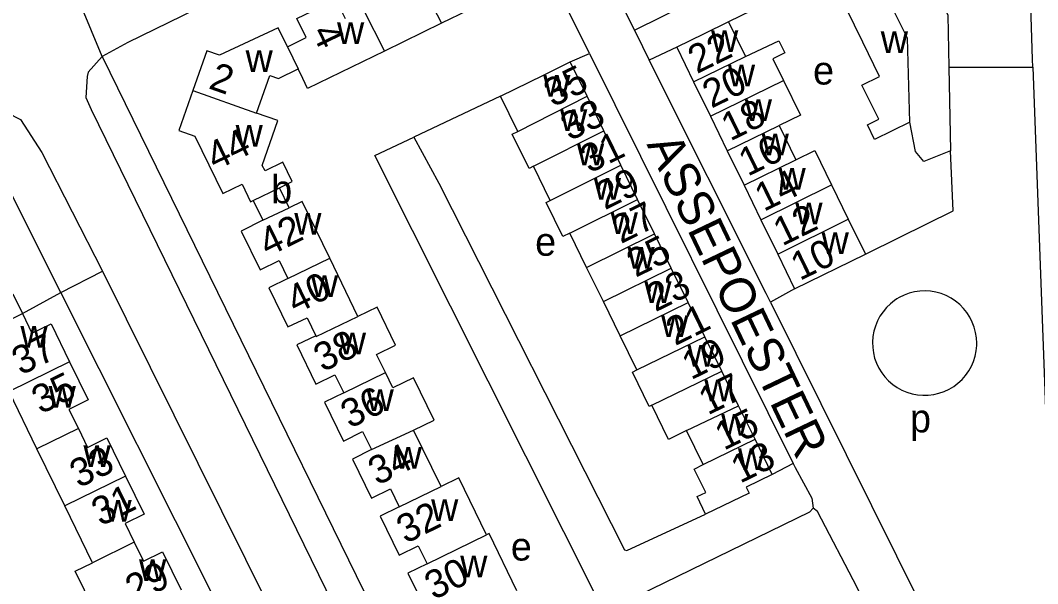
# Model space of a CAD drawing. Extents: x 159441 to 162086, y 388175 to 389787.
# Drawn here: x 161694.2 to 161838.6, y 388623.7 to 388703.5 of the extents above; entities that cross this region are included whole.
import ezdxf

# ---------------------------------------------------------------- set-up
doc = ezdxf.new("R2010")
doc.units = 0
for name, color, linetype in [('BLT_Basislijn', 7, 'Continuous'), ('BLT_Bebouwing', 7, 'Continuous'), ('BLT_Centroide', 7, 'Continuous'), ('BLT_Huisnummer', 7, 'Continuous'), ('BLT_Huisnummer_ tussenligend', 7, 'Continuous'), ('BLT_Onderverdeling_panden', 7, 'Continuous'), ('BLT_Straatnaam', 7, 'Continuous'), ('BLT_Vlakafsluiter', 7, 'Continuous')]:
    doc.layers.add(name, color=color, linetype=linetype)

msp = doc.modelspace()

# ---------------------------------------------------------------- linework, layer by layer
at = {"layer": 'BLT_Basislijn'}
for p, q in [((161787.37, 388699.71), (161783.47, 388697.87)), ((161774.98, 388698.85), (161803.89, 388640.69)), ((161826, 388696.91), (161826.22, 388685.02)), ((161837.9, 388696.91), (161841.3, 388605.81)), ((161699.94, 388664.93), (161705.87, 388667.98)), ((161705.87, 388667.98), (161767.18, 388544.52)), ((161694.49, 388661.96), (161699.94, 388664.93)), ((161804.09, 388665.47), (161800.65, 388663.59)), ((161800.65, 388663.59), (161829.12, 388606.33)), ((161803.89, 388640.69), (161800.93, 388639.14))]:
    msp.add_line(p, q, dxfattribs=at)
for points in [[(161837.9, 388696.91), (161837.86, 388698.05), (161834.76, 388795.59)], [(161785.58, 388747.05), (161785.56, 388745.89), (161785.48, 388744.73), (161785.31, 388743.59), (161785.06, 388742.46), (161784.74, 388741.34), (161784.34, 388740.26), (161783.86, 388739.2), (161783.31, 388738.18), (161782.7, 388737.2), (161782.02, 388736.27), (161781.27, 388735.38), (161780.29, 388734.37), (161768.65, 388728.46), (161769.65, 388725.53), (161772.18, 388720.46), (161781.36, 388702.15)], [(161774.98, 388698.85), (161774.36, 388700.1), (161762.24, 388724.2), (161759.59, 388724.85), (161709.46, 388700.41), (161705.83, 388698.4)], [(161781.36, 388702.15), (161809.35, 388715.97), (161808.82, 388717), (161817.35, 388721.8)], [(161817.35, 388721.8), (161825.86, 388704.28), (161826, 388696.91)], [(161808.03, 388709.84), (161794.7, 388703.31)], [(161781.36, 388702.15), (161782.49, 388699.82), (161783.47, 388697.87)], [(161705.83, 388698.4), (161703.83, 388696.17), (161703.67, 388695.55), (161703.52, 388692.57), (161704.25, 388690.87), (161758.4, 388580.27)], [(161705.83, 388698.4), (161762.65, 388582.4)], [(161772.25, 388697.63), (161774.98, 388698.85)], [(161800.65, 388663.59), (161800.05, 388664.79), (161783.47, 388697.87)], [(161826, 388696.91), (161837.9, 388696.91)], [(161762.34, 388692.77), (161750.03, 388686.97)], [(161687.38, 388689.93), (161692.29, 388690.47), (161694.21, 388689.46), (161697.24, 388684.8), (161705.87, 388667.98)], [(161699.94, 388664.93), (161687.38, 388689.93)], [(161826.22, 388685.02), (161822.44, 388683.51), (161821.26, 388684.93), (161820.43, 388689.09)], [(161779.55, 388620.77), (161777.5, 388619.65), (161776.7, 388620.38), (161744.51, 388684.36), (161750.03, 388686.97)], [(161750.03, 388686.97), (161753.61, 388680.46), (161779.93, 388628.43), (161780.3, 388628.36), (161791.44, 388633.52)], [(161819.02, 388672.8), (161826.59, 388676.52), (161826.22, 388685.02)], [(161814.13, 388670.38), (161819.02, 388672.8)], [(161761.67, 388541.67), (161721.66, 388621.74), (161699.94, 388664.93)], [(161829.94, 388657.76), (161829.9, 388658.53), (161829.78, 388659.29), (161829.59, 388660.03), (161829.31, 388660.75), (161828.96, 388661.44), (161828.55, 388662.09), (161828.07, 388662.68), (161827.53, 388663.23), (161826.93, 388663.72), (161826.29, 388664.14), (161825.61, 388664.5), (161824.89, 388664.78), (161824.15, 388664.99), (161823.39, 388665.11), (161822.62, 388665.16), (161821.86, 388665.13), (161821.1, 388665.02), (161820.35, 388664.83), (161819.63, 388664.56), (161818.94, 388664.22), (161818.61, 388664.02)], [(161818.61, 388664.02), (161818.29, 388663.81), (161817.68, 388663.34), (161817.13, 388662.8), (161816.64, 388662.22), (161816.2, 388661.58), (161815.84, 388660.9), (161815.55, 388660.19), (161815.34, 388659.45), (161815.2, 388658.69), (161815.15, 388657.92), (161815.17, 388657.16), (161815.27, 388656.39), (161815.45, 388655.65), (161815.71, 388654.92), (161816.04, 388654.23), (161816.45, 388653.57), (161816.91, 388652.96), (161817.44, 388652.4), (161818.03, 388651.9), (161818.66, 388651.46), (161819.33, 388651.1), (161820.04, 388650.8), (161820.78, 388650.58), (161821.54, 388650.43), (161822.3, 388650.37), (161823.07, 388650.38), (161823.83, 388650.48), (161824.58, 388650.65), (161825.31, 388650.9), (161826.01, 388651.22), (161826.67, 388651.62), (161827.28, 388652.08), (161827.85, 388652.6), (161828.36, 388653.18), (161828.8, 388653.81), (161829.18, 388654.48), (161829.48, 388655.18), (161829.71, 388655.92), (161829.86, 388656.67), (161829.94, 388657.44), (161829.94, 388657.76)], [(161803.89, 388640.69), (161804.17, 388640.11), (161806.53, 388635.77), (161806.72, 388634.36)], [(161806.72, 388634.36), (161806.19, 388633.81), (161779.99, 388621.01), (161779.55, 388620.77)], [(161791.4, 388596.45), (161791.95, 388596.72), (161818.81, 388610.19), (161819.02, 388610.52), (161812.98, 388623.09), (161807.36, 388633.88), (161806.72, 388634.36)]]:
    msp.add_lwpolyline(points, dxfattribs=at)
at = {"layer": 'BLT_Bebouwing'}
for p, q in [((161813.78, 388700.42), (161811.41, 388705.28)), ((161753.98, 388703.11), (161745.89, 388699.17)), ((161787.37, 388699.71), (161789.76, 388694.82)), ((161774.64, 388692.76), (161772.25, 388697.63)), ((161789.76, 388694.82), (161792.15, 388689.93)), ((161777.03, 388687.88), (161774.64, 388692.76)), ((161792.15, 388689.93), (161794.54, 388685.04)), ((161779.42, 388683.01), (161777.03, 388687.88)), ((161794.54, 388685.04), (161796.92, 388680.15)), ((161781.81, 388678.13), (161779.42, 388683.01)), ((161796.92, 388680.15), (161799.31, 388675.26)), ((161809.33, 388680.22), (161811.69, 388675.36)), ((161784.2, 388673.26), (161781.81, 388678.13)), ((161799.31, 388675.26), (161801.7, 388670.36)), ((161786.59, 388668.39), (161784.2, 388673.26)), ((161742.12, 388661.56), (161738.11, 388669.8)), ((161801.7, 388670.36), (161804.09, 388665.47)), ((161804.09, 388665.47), (161814.13, 388670.38)), ((161788.98, 388663.51), (161786.59, 388668.39)), ((161791.37, 388658.64), (161788.98, 388663.51)), ((161781.71, 388653.96), (161779.34, 388658.8)), ((161793.76, 388653.77), (161791.37, 388658.64)), ((161796.15, 388648.89), (161793.76, 388653.77)), ((161798.48, 388644.14), (161796.15, 388648.89)), ((161753.91, 388637.42), (161750.02, 388645.4)), ((161791.12, 388640.53), (161788.74, 388645.38)), ((161800.93, 388639.14), (161798.48, 388644.14))]:
    msp.add_line(p, q, dxfattribs=at)
for points in [[(161732.1, 388699.78), (161734.79, 388701.08), (161733.47, 388703.8), (161738.99, 388706.5), (161740.31, 388703.77)], [(161819.12, 388703.01), (161816.7, 388707.86)], [(161759.36, 388705.73), (161757.72, 388704.93), (161753.98, 388703.11)], [(161732.1, 388699.78), (161730.79, 388702.49), (161722.49, 388698.6), (161720.69, 388699.23), (161718.69, 388693.57)], [(161794.7, 388703.31), (161791.18, 388701.58), (161787.37, 388699.71)], [(161794.7, 388703.31), (161797.1, 388698.4)], [(161820.43, 388689.09), (161820.12, 388701), (161819.12, 388703.01)], [(161797.1, 388698.4), (161801.87, 388700.64), (161802.71, 388698.92), (161801, 388698.09), (161802.52, 388694.99)], [(161820.43, 388689.09), (161815.44, 388686.63), (161814.45, 388688.72), (161816.03, 388689.5), (161813.65, 388694.33), (161816.15, 388695.57), (161813.78, 388700.42)], [(161745.89, 388699.17), (161734.98, 388693.85), (161734.29, 388695.28), (161733.62, 388696.65)], [(161727.74, 388690.37), (161729.63, 388695.72), (161730.84, 388695.29), (161733.62, 388696.65)], [(161762.34, 388692.77), (161768.45, 388695.76), (161772.25, 388697.63)], [(161802.52, 388694.99), (161804.92, 388690.1), (161801.89, 388688.63)], [(161718.69, 388693.57), (161716.69, 388687.91), (161718.95, 388687.13), (161722.93, 388678.97), (161725.67, 388680.31)], [(161764.8, 388687.76), (161762.34, 388692.77)], [(161728.95, 388682.2), (161728.51, 388682.95), (161730.75, 388689.31), (161727.74, 388690.37)], [(161767.02, 388682.84), (161766.41, 388682.54), (161764.03, 388687.38), (161764.8, 388687.76)], [(161801.89, 388688.63), (161804.27, 388683.77)], [(161804.27, 388683.77), (161806.97, 388685.09), (161809.33, 388680.22)], [(161730.99, 388679.79), (161732.8, 388680.67), (161731.47, 388683.42), (161728.95, 388682.2)], [(161769.4, 388677.99), (161767.02, 388682.84)], [(161725.67, 388680.31), (161726.89, 388677.8), (161727.27, 388677.98)], [(161732.37, 388676.96), (161730.99, 388679.79)], [(161727.27, 388677.98), (161728.64, 388675.18)], [(161738.11, 388669.8), (161734.18, 388677.84), (161732.37, 388676.96)], [(161772.2, 388673.35), (161771.21, 388672.87), (161768.84, 388677.71), (161769.4, 388677.99)], [(161728.64, 388675.18), (161725.53, 388673.66), (161728.22, 388668.14), (161730.93, 388669.46), (161732.19, 388666.91)], [(161811.69, 388675.36), (161814.13, 388670.38)], [(161774.58, 388668.5), (161772.2, 388673.35)], [(161776.95, 388663.67), (161774.58, 388668.5)], [(161732.19, 388666.91), (161729.47, 388665.58), (161732.19, 388660.05), (161734.89, 388661.36), (161736.13, 388658.81)], [(161688.59, 388659.09), (161687.24, 388661.85), (161688.65, 388662.54), (161693.14, 388664.74), (161694.49, 388661.96)], [(161779.34, 388658.8), (161776.95, 388663.67)], [(161694.49, 388661.96), (161695.85, 388659.17), (161698.56, 388660.48), (161701.2, 388655.1)], [(161746.02, 388653.59), (161744.77, 388656.15), (161747.47, 388657.46), (161744.83, 388662.87), (161742.12, 388661.56)], [(161736.13, 388658.81), (161733.43, 388657.5), (161736.12, 388651.96), (161738.83, 388653.27), (161740.1, 388650.73)], [(161701.2, 388655.1), (161703.84, 388649.71), (161701.11, 388648.37), (161702.44, 388645.67)], [(161750.02, 388645.4), (161752.93, 388646.82), (161750, 388652.83), (161747.08, 388651.41), (161746.02, 388653.59)], [(161783.81, 388648.95), (161783.46, 388648.78), (161781.08, 388653.64), (161781.71, 388653.96)], [(161696.56, 388642.79), (161692.6, 388650.88)], [(161740.1, 388650.73), (161737.36, 388649.4), (161740.06, 388643.88), (161742.78, 388645.23), (161744.05, 388642.66)], [(161788.74, 388645.38), (161786.18, 388644.12), (161783.81, 388648.95)], [(161702.44, 388645.67), (161703.76, 388642.97), (161706.49, 388644.31), (161709.12, 388638.92)], [(161700.51, 388634.71), (161696.56, 388642.79)], [(161744.05, 388642.66), (161741.33, 388641.31), (161744.03, 388635.79), (161746.75, 388637.11), (161747.99, 388634.54)], [(161791.44, 388633.52), (161790.25, 388636), (161791.47, 388636.59), (161789.83, 388639.9), (161791.12, 388640.53)], [(161709.12, 388638.92), (161711.76, 388633.52), (161709.06, 388632.2), (161710.37, 388629.52)], [(161760.38, 388630.59), (161756.44, 388638.66), (161753.91, 388637.42)], [(161800.93, 388639.14), (161797.24, 388637.33), (161797.64, 388636.5), (161791.44, 388633.52)], [(161704.46, 388626.63), (161700.51, 388634.71)], [(161747.99, 388634.54), (161745.28, 388633.22), (161747.97, 388627.71), (161750.66, 388629.03), (161751.93, 388626.49)], [(161764.68, 388622.66), (161760.72, 388630.76), (161760.38, 388630.59)], [(161710.37, 388629.52), (161711.68, 388626.85), (161714.38, 388628.17), (161717.02, 388622.77)], [(161708.4, 388618.57), (161705.96, 388617.35), (161702.01, 388625.43), (161704.46, 388626.63)], [(161751.93, 388626.49), (161749.22, 388625.16), (161751.92, 388619.63), (161754.63, 388620.95), (161755.88, 388618.38)]]:
    msp.add_lwpolyline(points, dxfattribs=at)
at = {"layer": 'BLT_Onderverdeling_panden'}
for p, q in [((161750.97, 388708.97), (161753.98, 388703.11)), ((161742.89, 388705.02), (161745.89, 388699.17)), ((161732.1, 388699.78), (161733.62, 388696.65)), ((161789.76, 388694.82), (161797.1, 388698.4)), ((161792.15, 388689.93), (161802.52, 388694.99)), ((161718.69, 388693.57), (161727.74, 388690.37)), ((161764.8, 388687.76), (161774.64, 388692.76)), ((161767.02, 388682.84), (161777.03, 388687.88)), ((161794.54, 388685.04), (161801.89, 388688.63)), ((161796.92, 388680.15), (161804.27, 388683.77)), ((161769.4, 388677.99), (161779.42, 388683.01)), ((161727.27, 388677.98), (161730.99, 388679.79)), ((161799.31, 388675.26), (161809.33, 388680.22)), ((161772.2, 388673.35), (161781.81, 388678.13)), ((161728.64, 388675.18), (161732.37, 388676.96)), ((161801.7, 388670.36), (161811.69, 388675.36)), ((161774.58, 388668.5), (161784.2, 388673.26)), ((161732.19, 388666.91), (161738.11, 388669.8)), ((161776.95, 388663.67), (161786.59, 388668.39)), ((161779.34, 388658.8), (161788.98, 388663.51)), ((161688.59, 388659.09), (161694.49, 388661.96)), ((161781.71, 388653.96), (161791.37, 388658.64)), ((161701.2, 388655.1), (161692.6, 388650.88)), ((161740.1, 388650.73), (161746.02, 388653.59)), ((161783.81, 388648.95), (161793.76, 388653.77)), ((161788.74, 388645.38), (161796.15, 388648.89)), ((161702.44, 388645.67), (161696.56, 388642.79)), ((161744.05, 388642.66), (161750.02, 388645.4)), ((161791.12, 388640.53), (161798.48, 388644.14)), ((161709.12, 388638.92), (161700.51, 388634.71)), ((161747.99, 388634.54), (161753.91, 388637.42)), ((161751.93, 388626.49), (161760.38, 388630.59)), ((161710.37, 388629.52), (161704.46, 388626.63))]:
    msp.add_line(p, q, dxfattribs=at)
msp.add_lwpolyline([(161736.13, 388658.81), (161736.2, 388658.7), (161742.12, 388661.56)], dxfattribs=at)
at = {"layer": 'BLT_Vlakafsluiter'}
msp.add_line((161705.83, 388698.4), (161702.78, 388705.67), dxfattribs=at)

# ---------------------------------------------------------------- texts
at = {"layer": 'BLT_Centroide'}
for s, p in [('w', (161739.15, 388700.19)), ('w', (161792.23, 388699.06)), ('w', (161816.32, 388698.88)), ('w', (161726.17, 388696.22)), ('w', (161794.62, 388694.16)), ('e', (161806.71, 388694.43)), ('w', (161768.41, 388692.72)), ('w', (161797.02, 388689.28)), ('w', (161770.8, 388687.84)), ('w', (161724.75, 388685.64)), ('w', (161799.41, 388684.38)), ('w', (161773.2, 388682.97)), ('w', (161801.8, 388679.5)), ('b', (161729.81, 388677.59)), ('w', (161775.59, 388678.09)), ('w', (161804.19, 388674.59)), ('w', (161733.08, 388673.16)), ('w', (161777.98, 388673.22)), ('e', (161767.27, 388670.15)), ('w', (161807.92, 388670.38)), ('w', (161780.37, 388668.34)), ('w', (161735.44, 388664.31)), ('w', (161782.76, 388663.47)), ('w', (161785.15, 388658.62)), ('w', (161694.22, 388657.11)), ('w', (161739.41, 388656.19)), ('w', (161788.88, 388654.41)), ('w', (161698.22, 388648.61)), ('w', (161791.27, 388649.53)), ('w', (161743.34, 388648.12)), ('w', (161793.66, 388644.66)), ('p', (161820.47, 388645.11)), ('w', (161703.16, 388640.19)), ('w', (161747.33, 388639.97)), ('w', (161796.05, 388639.78)), ('w', (161706.14, 388632.45)), ('w', (161752.5, 388632.56)), ('e', (161763.82, 388626.93)), ('w', (161711.05, 388624.03)), ('w', (161756.63, 388624.56))]:
    msp.add_text(s, height=4, dxfattribs=at).set_placement(p)
at = {"layer": 'BLT_Huisnummer'}
for s, rotation, p in [('4', 295.8679, (161735.48, 388701.86)), ('22', 26.034, (161790.22, 388695.9)), ('2', 340.5398, (161720.77, 388693.93)), ('35', 26.1205, (161769.78, 388691.16)), ('18', 26.034, (161794.95, 388686.34)), ('44', 26.019, (161721.87, 388682.17)), ('29', 26.1205, (161777.16, 388676.59)), ('14', 26.034, (161799.72, 388676.35)), ('42', 26.2599, (161729.33, 388669.94)), ('25', 26.1205, (161781.53, 388667.02)), ('10', 26.034, (161804.82, 388666.56)), ('21', 26.1205, (161787.13, 388657.33)), ('37', 26.0328, (161694.27, 388653.14)), ('17', 26.1205, (161791.76, 388647.48)), ('36', 26.2599, (161740.96, 388645.59)), ('13', 26.1205, (161796.35, 388637.81)), ('31', 26.0328, (161705.59, 388631.74)), ('32', 26.2599, (161748.88, 388629.26))]:
    msp.add_text(s, height=4, rotation=rotation, dxfattribs=at).set_placement(p)
at = {"layer": 'BLT_Huisnummer_ tussenligend'}
for s, rotation, p in [('20', 26.034, (161792.29, 388691)), ('33', 26.1205, (161772.17, 388686.37)), ('31', 26.1205, (161774.97, 388681.78)), ('16', 26.034, (161797.43, 388681.34)), ('27', 26.1205, (161779.44, 388671.8)), ('12', 26.034, (161802.34, 388671.46)), ('40', 26.2599, (161733.27, 388661.82)), ('23', 26.1205, (161784.34, 388662.13)), ('38', 26.2599, (161737.12, 388653.6)), ('19', 26.1205, (161789.38, 388652.48)), ('35', 26.0328, (161697.09, 388647.63)), ('15', 26.1205, (161794.06, 388642.49)), ('33', 26.0328, (161702.49, 388637.15)), ('34', 26.2599, (161744.86, 388637.52)), ('30', 26.2599, (161752.87, 388621.29)), ('29', 26.0328, (161710.38, 388620.83))]:
    msp.add_text(s, height=4, rotation=rotation, dxfattribs=at).set_placement(p)
at = {"layer": 'BLT_Straatnaam'}
msp.add_text('ASSEPOESTER', height=5, rotation=295.5288, dxfattribs=at).set_placement((161783.04, 388685.96))

doc.saveas('drawing.dxf')
